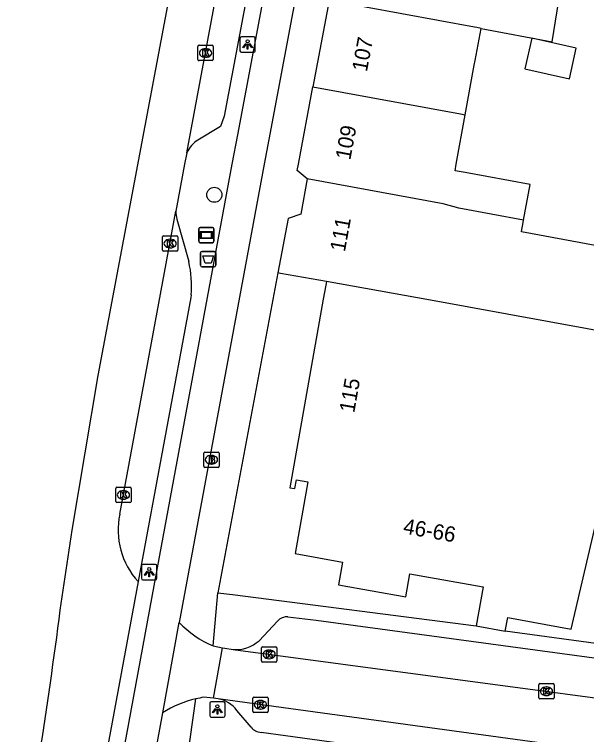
# Model space of a CAD drawing. Extents: x 161845 to 162341, y 381620 to 382158.
# Drawn here: x 161855.67 to 161892.92, y 381712.86 to 381759.75 of the extents above; entities that cross this region are included whole.
import ezdxf

# ---------------------------------------------------------------- set-up
doc = ezdxf.new("R2010")
doc.units = 0
for name, color, linetype in [('IMGEO_Afvalbak', 7, 'Continuous'), ('IMGEO_Boom', 7, 'Continuous'), ('IMGEO_Brandkraan', 7, 'Continuous'), ('IMGEO_Fietspad_gesloten', 7, 'Continuous'), ('IMGEO_Kolk', 7, 'Continuous'), ('IMGEO_Lichtpunt', 7, 'Continuous'), ('IMGEO_OVBaan_gesloten', 7, 'Continuous'), ('IMGEO_OVBaan_open', 7, 'Continuous'), ('IMGEO_Pand', 7, 'Continuous'), ('IMGEO_Pand_nummerreeks', 7, 'Continuous'), ('IMGEO_Parkeervlak_open', 7, 'Continuous'), ('IMGEO_Reclamebord', 7, 'Continuous'), ('IMGEO_Rijbaan_lokaal_gesloten', 7, 'Continuous'), ('IMGEO_Rijbaan_lokaal_open', 7, 'Continuous'), ('IMGEO_Voetpad_open', 7, 'Continuous')]:
    doc.layers.add(name, color=color, linetype=linetype)

msp = doc.modelspace()

# ---------------------------------------------------------------- linework, layer by layer
at = {"layer": 'IMGEO_Afvalbak'}
for p, q in [((161867.787, 381743.416), (161867.787, 381744.216)), ((161867.787, 381744.216), (161867.787, 381743.416)), ((161867.887, 381744.316), (161868.677, 381744.316)), ((161868.677, 381744.316), (161867.887, 381744.316)), ((161868.777, 381744.216), (161868.777, 381743.416)), ((161868.777, 381743.416), (161868.777, 381744.216)), ((161868.677, 381743.316), (161867.887, 381743.316)), ((161867.887, 381743.316), (161868.677, 381743.316))]:
    msp.add_line(p, q, dxfattribs=at)
msp.add_lwpolyline([(161867.93, 381744.03), (161868.634, 381744.03), (161868.485, 381743.56), (161868.079, 381743.56), (161867.93, 381744.03)], dxfattribs=at)
for centre, start, end in [((161867.887, 381744.216), 90, 180), ((161867.887, 381744.216), 90, 180), ((161868.677, 381744.216), 0, 90), ((161868.677, 381744.216), 360, 90), ((161867.887, 381743.416), 180, 270), ((161867.887, 381743.416), 180, 270), ((161868.677, 381743.416), 270, 0), ((161868.677, 381743.416), 270, 0)]:
    msp.add_arc(centre, 0.1, start, end, dxfattribs=at)
at = {"layer": 'IMGEO_Boom'}
msp.add_circle((161868.686, 381748.003), 0.489, dxfattribs=at)
at = {"layer": 'IMGEO_Brandkraan'}
for p, q in [((161867.998, 381730.329), (161867.998, 381731.181)), ((161868.073, 381731.255), (161868.925, 381731.255)), ((161868.486, 381731.035), (161868.511, 381731.035)), ((161868.999, 381731.181), (161868.999, 381730.329)), ((161868.509, 381730.475), (161868.484, 381730.475)), ((161868.925, 381730.255), (161868.073, 381730.255))]:
    msp.add_line(p, q, dxfattribs=at)
for points in [[(161867.998, 381730.329), (161867.998, 381731.181)], [(161868.073, 381731.255), (161868.925, 381731.255)], [(161868.346, 381730.955), (161868.346, 381730.555), (161868.559, 381730.555)], [(161868.577, 381730.955), (161868.346, 381730.955)], [(161868.525, 381730.874), (161868.471, 381730.874), (161868.471, 381730.798)], [(161868.999, 381731.181), (161868.999, 381730.329)], [(161868.471, 381730.798), (161868.524, 381730.798)], [(161868.533, 381730.722), (161868.471, 381730.722), (161868.471, 381730.641)], [(161868.471, 381730.641), (161868.533, 381730.641)], [(161868.925, 381730.255), (161868.073, 381730.255)]]:
    msp.add_lwpolyline(points, dxfattribs=at)
for centre, radius, start, end in [((161868.075, 381731.179), 0.0765, 91.552, 178.448), ((161868.075, 381731.179), 0.0765, 91.552, 178.448), ((161868.526, 381730.836), 0.0379, 267.8285, 90.9355), ((161868.581, 381730.81), 0.145, 59.4692, 91.5367), ((161868.606, 381730.857), 0.0922, 285.5137, 58.1501), ((161868.923, 381731.179), 0.0765, 1.552, 88.448), ((161868.923, 381731.179), 0.0765, 1.552, 88.448), ((161868.534, 381730.681), 0.0404, 269.8759, 90.5077), ((161868.565, 381730.806), 0.251, 268.6676, 293.5347), ((161868.611, 381730.665), 0.105, 301.3115, 78.989), ((161868.075, 381730.331), 0.0765, 181.552, 268.448), ((161868.075, 381730.331), 0.0765, 181.552, 268.448), ((161868.923, 381730.331), 0.0765, 271.552, 358.448), ((161868.923, 381730.331), 0.0765, 271.552, 358.448)]:
    msp.add_arc(centre, radius, start, end, dxfattribs=at)
for centre, major_axis, ratio, start_param, end_param in [((161868.485, 381730.755), (-0.387, 0.002), 0.722429, 4.712389, 7.853982), ((161868.51, 381730.755), (-0.39, 0.002), 0.717154, 1.570796, 4.712389)]:
    msp.add_ellipse(centre, major_axis=major_axis, ratio=ratio, start_param=start_param, end_param=end_param, dxfattribs=at)
at = {"layer": 'IMGEO_Fietspad_gesloten'}
for points in [[(161857.316, 381682.246), (161862.987, 381712.892), (161864.774, 381722.548), (161869.854, 381750), (161870.207, 381751.91), (161895.081, 381884.229), (161897.858, 381899.101), (161916.698, 382000), (161921.558, 382026.031), (161926.346, 382051.921)], [(161907.39, 381938.834), (161899.866, 381898.705), (161897.095, 381883.929), (161872.236, 381751.615), (161871.936, 381750), (161866.402, 381720.165)], [(161859.158, 381680.785), (161865.321, 381714.277)]]:
    msp.add_lwpolyline(points, dxfattribs=at)
at = {"layer": 'IMGEO_Kolk'}
for p, q in [((161867.613, 381756.812), (161867.613, 381757.664)), ((161867.688, 381757.738), (161868.54, 381757.738)), ((161868.614, 381757.664), (161868.614, 381756.812)), ((161868.101, 381757.518), (161868.126, 381757.518)), ((161868.54, 381756.738), (161867.688, 381756.738)), ((161868.124, 381756.958), (161868.099, 381756.958)), ((161865.307, 381744.406), (161865.307, 381745.258)), ((161865.382, 381745.332), (161866.234, 381745.332)), ((161865.795, 381745.112), (161865.82, 381745.112)), ((161866.308, 381745.258), (161866.308, 381744.406)), ((161865.818, 381744.552), (161865.793, 381744.552)), ((161866.234, 381744.332), (161865.382, 381744.332)), ((161862.266, 381728.037), (161862.266, 381728.889)), ((161862.341, 381728.963), (161863.193, 381728.963)), ((161862.754, 381728.743), (161862.779, 381728.743)), ((161863.267, 381728.889), (161863.267, 381728.037)), ((161862.777, 381728.183), (161862.752, 381728.183)), ((161863.193, 381727.963), (161862.341, 381727.963)), ((161871.754, 381717.654), (161871.754, 381718.506)), ((161871.829, 381718.58), (161872.681, 381718.58)), ((161872.242, 381718.36), (161872.267, 381718.36)), ((161872.755, 381718.506), (161872.755, 381717.654)), ((161872.265, 381717.8), (161872.24, 381717.8)), ((161872.681, 381717.58), (161871.829, 381717.58)), ((161889.808, 381715.255), (161889.808, 381716.107)), ((161889.883, 381716.181), (161890.735, 381716.181)), ((161890.296, 381715.961), (161890.321, 381715.961)), ((161890.809, 381716.107), (161890.809, 381715.255)), ((161890.319, 381715.401), (161890.294, 381715.401)), ((161871.187, 381714.373), (161871.187, 381715.225)), ((161871.262, 381715.299), (161872.114, 381715.299)), ((161871.675, 381715.079), (161871.7, 381715.079)), ((161872.188, 381715.225), (161872.188, 381714.373)), ((161890.735, 381715.181), (161889.883, 381715.181)), ((161871.698, 381714.519), (161871.673, 381714.519)), ((161872.114, 381714.299), (161871.262, 381714.299))]:
    msp.add_line(p, q, dxfattribs=at)
for points in [[(161867.613, 381756.812), (161867.613, 381757.664)], [(161867.688, 381757.738), (161868.54, 381757.738)], [(161868.614, 381757.664), (161868.614, 381756.812)], [(161867.934, 381757.438), (161868.057, 381757.438), (161868.057, 381757.287), (161868.187, 381757.438), (161868.351, 381757.438), (161868.205, 381757.287), (161868.358, 381757.038), (161868.206, 381757.038), (161868.121, 381757.202), (161868.057, 381757.135), (161868.057, 381757.038), (161867.934, 381757.038), (161867.934, 381757.438)], [(161868.54, 381756.738), (161867.688, 381756.738)], [(161865.307, 381744.406), (161865.307, 381745.258)], [(161865.382, 381745.332), (161866.234, 381745.332)], [(161865.628, 381745.032), (161865.751, 381745.032), (161865.751, 381744.881), (161865.881, 381745.032), (161866.045, 381745.032), (161865.899, 381744.881), (161866.052, 381744.632), (161865.9, 381744.632), (161865.815, 381744.796), (161865.751, 381744.729), (161865.751, 381744.632), (161865.628, 381744.632), (161865.628, 381745.032)], [(161866.308, 381745.258), (161866.308, 381744.406)], [(161866.234, 381744.332), (161865.382, 381744.332)], [(161862.266, 381728.037), (161862.266, 381728.889)], [(161862.341, 381728.963), (161863.193, 381728.963)], [(161862.587, 381728.663), (161862.71, 381728.663), (161862.71, 381728.512), (161862.84, 381728.663), (161863.004, 381728.663), (161862.858, 381728.512), (161863.011, 381728.263), (161862.859, 381728.263), (161862.774, 381728.427), (161862.71, 381728.36), (161862.71, 381728.263), (161862.587, 381728.263), (161862.587, 381728.663)], [(161863.267, 381728.889), (161863.267, 381728.037)], [(161863.193, 381727.963), (161862.341, 381727.963)], [(161871.754, 381717.654), (161871.754, 381718.506)], [(161871.829, 381718.58), (161872.681, 381718.58)], [(161872.075, 381718.28), (161872.198, 381718.28), (161872.198, 381718.129), (161872.328, 381718.28), (161872.492, 381718.28), (161872.346, 381718.129), (161872.499, 381717.88), (161872.347, 381717.88), (161872.262, 381718.044), (161872.198, 381717.977), (161872.198, 381717.88), (161872.075, 381717.88), (161872.075, 381718.28)], [(161872.755, 381718.506), (161872.755, 381717.654)], [(161872.681, 381717.58), (161871.829, 381717.58)], [(161889.808, 381715.255), (161889.808, 381716.107)], [(161889.883, 381716.181), (161890.735, 381716.181)], [(161890.129, 381715.881), (161890.252, 381715.881), (161890.252, 381715.73), (161890.382, 381715.881), (161890.546, 381715.881), (161890.4, 381715.73), (161890.553, 381715.481), (161890.401, 381715.481), (161890.316, 381715.645), (161890.252, 381715.578), (161890.252, 381715.481), (161890.129, 381715.481), (161890.129, 381715.881)], [(161890.809, 381716.107), (161890.809, 381715.255)], [(161871.187, 381714.373), (161871.187, 381715.225)], [(161871.262, 381715.299), (161872.114, 381715.299)], [(161871.508, 381714.999), (161871.631, 381714.999), (161871.631, 381714.848), (161871.761, 381714.999), (161871.925, 381714.999), (161871.779, 381714.848), (161871.932, 381714.599), (161871.78, 381714.599), (161871.695, 381714.763), (161871.631, 381714.696), (161871.631, 381714.599), (161871.508, 381714.599), (161871.508, 381714.999)], [(161872.188, 381715.225), (161872.188, 381714.373)], [(161890.735, 381715.181), (161889.883, 381715.181)], [(161872.114, 381714.299), (161871.262, 381714.299)]]:
    msp.add_lwpolyline(points, dxfattribs=at)
for centre, start, end in [((161867.69, 381757.662), 91.552, 178.448), ((161867.69, 381757.662), 91.552, 178.448), ((161868.538, 381757.662), 1.552, 88.448), ((161868.538, 381757.662), 1.552, 88.448), ((161867.69, 381756.814), 181.552, 268.448), ((161867.69, 381756.814), 181.552, 268.448), ((161868.538, 381756.814), 271.552, 358.448), ((161868.538, 381756.814), 271.552, 358.448), ((161865.384, 381745.256), 91.552, 178.448), ((161865.384, 381745.256), 91.552, 178.448), ((161866.232, 381745.256), 1.552, 88.448), ((161866.232, 381745.256), 1.552, 88.448), ((161865.384, 381744.408), 181.552, 268.448), ((161865.384, 381744.408), 181.552, 268.448), ((161866.232, 381744.408), 271.552, 358.448), ((161866.232, 381744.408), 271.552, 358.448), ((161862.343, 381728.887), 91.552, 178.448), ((161862.343, 381728.887), 91.552, 178.448), ((161863.191, 381728.887), 1.552, 88.448), ((161863.191, 381728.887), 1.552, 88.448), ((161862.343, 381728.039), 181.552, 268.448), ((161862.343, 381728.039), 181.552, 268.448), ((161863.191, 381728.039), 271.552, 358.448), ((161863.191, 381728.039), 271.552, 358.448), ((161871.831, 381718.504), 91.552, 178.448), ((161871.831, 381718.504), 91.552, 178.448), ((161872.679, 381718.504), 1.552, 88.448), ((161872.679, 381718.504), 1.552, 88.448), ((161871.831, 381717.656), 181.552, 268.448), ((161871.831, 381717.656), 181.552, 268.448), ((161872.679, 381717.656), 271.552, 358.448), ((161872.679, 381717.656), 271.552, 358.448), ((161889.885, 381716.105), 91.552, 178.448), ((161889.885, 381716.105), 91.552, 178.448), ((161890.733, 381716.105), 1.552, 88.448), ((161890.733, 381716.105), 1.552, 88.448), ((161871.264, 381715.223), 91.552, 178.448), ((161871.264, 381715.223), 91.552, 178.448), ((161872.112, 381715.223), 1.552, 88.448), ((161872.112, 381715.223), 1.552, 88.448), ((161889.885, 381715.257), 181.552, 268.448), ((161889.885, 381715.257), 181.552, 268.448), ((161890.733, 381715.257), 271.552, 358.448), ((161890.733, 381715.257), 271.552, 358.448), ((161871.264, 381714.375), 181.552, 268.448), ((161871.264, 381714.375), 181.552, 268.448), ((161872.112, 381714.375), 271.552, 358.448), ((161872.112, 381714.375), 271.552, 358.448)]:
    msp.add_arc(centre, 0.0765, start, end, dxfattribs=at)
for centre, major_axis, ratio, start_param, end_param in [((161868.1, 381757.238), (-0.387, 0.002), 0.722429, 4.712389, 7.853982), ((161868.125, 381757.238), (-0.39, 0.002), 0.717154, 1.570796, 4.712389), ((161865.794, 381744.832), (-0.387, 0.002), 0.722429, 4.712389, 7.853982), ((161865.819, 381744.832), (-0.39, 0.002), 0.717154, 1.570796, 4.712389), ((161862.753, 381728.463), (-0.387, 0.002), 0.722429, 4.712389, 7.853982), ((161862.778, 381728.463), (-0.39, 0.002), 0.717154, 1.570796, 4.712389), ((161872.241, 381718.08), (-0.387, 0.002), 0.722429, 4.712389, 7.853982), ((161872.266, 381718.08), (-0.39, 0.002), 0.717154, 1.570796, 4.712389), ((161890.295, 381715.681), (-0.387, 0.002), 0.722429, 4.712389, 7.853982), ((161890.32, 381715.681), (-0.39, 0.002), 0.717154, 1.570796, 4.712389), ((161871.674, 381714.799), (-0.387, 0.002), 0.722429, 4.712389, 7.853982), ((161871.699, 381714.799), (-0.39, 0.002), 0.717154, 1.570796, 4.712389)]:
    msp.add_ellipse(centre, major_axis=major_axis, ratio=ratio, start_param=start_param, end_param=end_param, dxfattribs=at)
at = {"layer": 'IMGEO_Lichtpunt'}
for p, q in [((161870.351, 381758.194), (161870.351, 381757.387)), ((161870.351, 381758.194), (161870.351, 381757.387)), ((161871.253, 381758.289), (161870.445, 381758.289)), ((161871.253, 381758.289), (161870.445, 381758.289)), ((161871.347, 381757.387), (161871.347, 381758.194)), ((161871.347, 381757.387), (161871.347, 381758.194)), ((161870.445, 381757.293), (161871.253, 381757.293)), ((161870.445, 381757.293), (161871.253, 381757.293)), ((161863.946, 381723.839), (161863.946, 381723.032)), ((161863.946, 381723.839), (161863.946, 381723.032)), ((161864.848, 381723.934), (161864.04, 381723.934)), ((161864.848, 381723.934), (161864.04, 381723.934)), ((161864.942, 381723.032), (161864.942, 381723.839)), ((161864.942, 381723.032), (161864.942, 381723.839)), ((161864.04, 381722.938), (161864.848, 381722.938)), ((161864.04, 381722.938), (161864.848, 381722.938)), ((161869.288, 381714.992), (161868.48, 381714.992)), ((161869.288, 381714.992), (161868.48, 381714.992)), ((161868.386, 381714.897), (161868.386, 381714.09)), ((161868.386, 381714.897), (161868.386, 381714.09)), ((161869.382, 381714.09), (161869.382, 381714.897)), ((161869.382, 381714.09), (161869.382, 381714.897)), ((161868.48, 381713.996), (161869.288, 381713.996)), ((161868.48, 381713.996), (161869.288, 381713.996))]:
    msp.add_line(p, q, dxfattribs=at)
for points in [[(161870.725, 381757.858), (161870.764, 381757.83), (161870.576, 381757.568), (161870.538, 381757.595), (161870.725, 381757.858)], [(161870.827, 381757.81), (161870.874, 381757.81), (161870.874, 381757.488), (161870.827, 381757.488), (161870.827, 381757.81)], [(161870.937, 381757.83), (161870.975, 381757.857), (161871.162, 381757.595), (161871.123, 381757.567), (161870.937, 381757.83)], [(161864.32, 381723.503), (161864.359, 381723.475), (161864.171, 381723.213), (161864.133, 381723.24), (161864.32, 381723.503)], [(161864.422, 381723.455), (161864.469, 381723.455), (161864.469, 381723.133), (161864.422, 381723.133), (161864.422, 381723.455)], [(161864.532, 381723.475), (161864.57, 381723.502), (161864.757, 381723.24), (161864.718, 381723.212), (161864.532, 381723.475)], [(161868.76, 381714.561), (161868.799, 381714.533), (161868.611, 381714.271), (161868.573, 381714.298), (161868.76, 381714.561)], [(161868.862, 381714.513), (161868.909, 381714.513), (161868.909, 381714.191), (161868.862, 381714.191), (161868.862, 381714.513)], [(161868.972, 381714.533), (161869.01, 381714.56), (161869.197, 381714.298), (161869.158, 381714.27), (161868.972, 381714.533)]]:
    msp.add_lwpolyline(points, dxfattribs=at)
for centre in [(161870.85, 381757.992), (161864.445, 381723.637), (161868.885, 381714.695)]:
    msp.add_circle(centre, 0.0994, dxfattribs=at)
for centre, start, end in [((161870.445, 381758.194), 90, 180), ((161870.445, 381758.194), 90, 180), ((161871.253, 381758.194), 0, 90), ((161871.253, 381758.194), 0, 90), ((161870.445, 381757.387), 180, 270), ((161870.445, 381757.387), 180, 270), ((161871.253, 381757.387), 270, 0), ((161871.253, 381757.387), 270, 360), ((161864.04, 381723.839), 90, 180), ((161864.04, 381723.839), 90, 180), ((161864.848, 381723.839), 0, 90), ((161864.848, 381723.839), 0, 90), ((161864.04, 381723.032), 180, 270), ((161864.04, 381723.032), 180, 270), ((161864.848, 381723.032), 270, 0), ((161864.848, 381723.032), 270, 360), ((161868.48, 381714.897), 90, 180), ((161868.48, 381714.897), 90, 180), ((161869.288, 381714.897), 0, 90), ((161869.288, 381714.897), 0, 90), ((161868.48, 381714.09), 180, 270), ((161868.48, 381714.09), 180, 270), ((161869.288, 381714.09), 270, 0), ((161869.288, 381714.09), 270, 360)]:
    msp.add_arc(centre, 0.0946, start, end, dxfattribs=at)
at = {"layer": 'IMGEO_OVBaan_gesloten'}
msp.add_lwpolyline([(161858.651, 381720.96), (161859.425, 381726.158), (161861.132, 381736.231), (161869.606, 381781.344), (161897.211, 381928.16), (161915.531, 382025.949), (161915.767, 382027.092)], dxfattribs=at)
msp.add_arc((161552.98, 381759.757), 308.123, 349.22229, 352.7665, dxfattribs=at)
at = {"layer": 'IMGEO_OVBaan_open'}
for points in [[(161862.533, 381727.211), (161866.175, 381746.944)], [(161866.247, 381746.424), (161867.019, 381743.652)], [(161867.182, 381741.481), (161867.15, 381741.313), (161863.721, 381722.825)]]:
    msp.add_lwpolyline(points, dxfattribs=at)
for centre, radius, start, end in [((161867.977, 381746.929), 1.802, 179.5084, 196.2579), ((161860.197, 381742.048), 7.008, 355.3577, 13.2298), ((161867.337, 381726.158), 4.918, 167.6427, 222.6685)]:
    msp.add_arc(centre, radius, start, end, dxfattribs=at)
at = {"layer": 'IMGEO_Pand'}
for points in [[(161886.047, 381758.842), (161890.679, 381757.965), (161891.624, 381763.915)], [(161876.159, 381760.654), (161875.101, 381755.029)], [(161886.047, 381758.842), (161885.767, 381758.895), (161885.618, 381758.922), (161876.159, 381760.654)], [(161885.019, 381753.201), (161885.608, 381756.435), (161885.666, 381756.751), (161886.047, 381758.842)], [(161892.25, 381757.56), (161889.36, 381758.212), (161888.909, 381756.213), (161891.798, 381755.561), (161892.25, 381757.56)], [(161874.727, 381749.038), (161874.078, 381749.589), (161874.155, 381750), (161875.101, 381755.029)], [(161875.101, 381755.029), (161884.714, 381753.269), (161885.019, 381753.201)], [(161888.814, 381746.358), (161889.239, 381748.671), (161885.018, 381749.447), (161884.356, 381749.569), (161884.435, 381750), (161885.019, 381753.201)], [(161874.727, 381749.038), (161874.307, 381746.749), (161873.489, 381746.458), (161872.827, 381742.933)], [(161888.814, 381746.358), (161884.593, 381747.134), (161883.593, 381747.414), (161874.727, 381749.038)], [(161895.471, 381738.811), (161896.758, 381744.105), (161888.673, 381745.589), (161888.7, 381745.739), (161888.742, 381745.964), (161888.762, 381746.077), (161888.814, 381746.358)], [(161875.98, 381742.352), (161872.993, 381742.884), (161872.827, 381742.933)], [(161875.98, 381742.352), (161875.937, 381742.11), (161875.779, 381741.216), (161873.608, 381728.93), (161873.926, 381728.874), (161874.026, 381729.438), (161874.777, 381729.306), (161873.953, 381724.639), (161877.038, 381724.095), (161876.775, 381722.602), (161881.147, 381721.831), (161881.41, 381723.315), (161886.186, 381722.471), (161885.74, 381719.94)], [(161895.471, 381738.811), (161882.761, 381741.144), (161875.98, 381742.352)], [(161887.622, 381719.595), (161887.784, 381720.479), (161891.913, 381719.721), (161893.893, 381728.171), (161908.006, 381724.477), (161906.933, 381720.378), (161912.06, 381719.035), (161913.133, 381723.134)], [(161885.74, 381719.94), (161887.622, 381719.595)]]:
    msp.add_lwpolyline(points, dxfattribs=at)
at = {"layer": 'IMGEO_Parkeervlak_open'}
msp.add_lwpolyline([(161872.113, 381767.878), (161869.329, 381753.124), (161869.093, 381752.446), (161867.616, 381751.571)], dxfattribs=at)
msp.add_arc((161868.661, 381749.96), 1.921, 122.968, 156.1916, dxfattribs=at)
at = {"layer": 'IMGEO_Reclamebord'}
for p, q in [((161867.766, 381745.88), (161868.556, 381745.88)), ((161868.556, 381745.88), (161867.766, 381745.88)), ((161867.666, 381744.98), (161867.666, 381745.78)), ((161867.666, 381745.78), (161867.666, 381744.98)), ((161868.656, 381745.78), (161868.656, 381744.98)), ((161868.656, 381744.98), (161868.656, 381745.78)), ((161868.556, 381744.88), (161867.766, 381744.88)), ((161867.766, 381744.88), (161868.556, 381744.88))]:
    msp.add_line(p, q, dxfattribs=at)
for points in [[(161867.767, 381745.612), (161868.555, 381745.612), (161868.555, 381745.148), (161867.767, 381745.148), (161867.767, 381745.612)], [(161867.832, 381745.547), (161867.832, 381745.213), (161868.49, 381745.213), (161868.49, 381745.547), (161867.832, 381745.547)]]:
    msp.add_lwpolyline(points, dxfattribs=at)
for centre, start, end in [((161867.766, 381745.78), 90, 180), ((161867.766, 381745.78), 90, 180), ((161868.556, 381745.78), 0, 90), ((161868.556, 381745.78), 360, 90), ((161867.766, 381744.98), 180, 270), ((161867.766, 381744.98), 180, 270), ((161868.556, 381744.98), 270, 0), ((161868.556, 381744.98), 270, 0)]:
    msp.add_arc(centre, 0.1, start, end, dxfattribs=at)
at = {"layer": 'IMGEO_Rijbaan_lokaal_gesloten'}
for points in [[(161866.904, 381750.735), (161870.759, 381771.481)], [(161866.904, 381750.735), (161866.739, 381750), (161866.175, 381746.944)], [(161863.721, 381722.825), (161861.927, 381713.087), (161861.385, 381710.143), (161860.718, 381707.24), (161860.66, 381706.996), (161860.336, 381705.821)]]:
    msp.add_lwpolyline(points, dxfattribs=at)
at = {"layer": 'IMGEO_Rijbaan_lokaal_open'}
for points in [[(161865.321, 381714.277), (161866.402, 381720.165)], [(161868.609, 381718.629), (161869.225, 381718.514)], [(161868.626, 381715.237), (161869.225, 381718.514)], [(161869.225, 381718.514), (161869.365, 381718.483), (161869.911, 381718.389)], [(161869.911, 381718.389), (161898.507, 381714.581)], [(161868.626, 381715.237), (161867.989, 381715.284)], [(161868.939, 381715.193), (161868.626, 381715.237)], [(161909.378, 381709.658), (161873.668, 381714.537), (161868.939, 381715.193)]]:
    msp.add_lwpolyline(points, dxfattribs=at)
for centre, radius, start, end in [((161871.05, 381724.49), 6.349, 222.9381, 247.3886), ((161869.087, 381708.336), 7.034, 103.2185, 122.3752), ((161869.008, 381708.739), 6.624, 98.8455, 103.342)]:
    msp.add_arc(centre, radius, start, end, dxfattribs=at)
at = {"layer": 'IMGEO_Voetpad_open'}
for points in [[(161872.827, 381742.933), (161868.92, 381722.091)], [(161868.609, 381718.629), (161868.92, 381722.091)], [(161868.92, 381722.091), (161869.859, 381721.971), (161885.74, 381719.94)], [(161871.6, 381718.966), (161872.79, 381720.242)], [(161873.478, 381720.533), (161875.325, 381720.308), (161898.861, 381717.122)], [(161898.959, 381718.053), (161887.622, 381719.595)], [(161866.911, 381711.167), (161867.479, 381715.184)], [(161871.079, 381713.333), (161870.151, 381714.435)], [(161906.334, 381708.242), (161873.323, 381712.777), (161871.736, 381712.996)]]:
    msp.add_lwpolyline(points, dxfattribs=at)
for centre, radius, start, end in [((161873.469, 381719.595), 0.938, 89.471, 136.3823), ((161870.043, 381720.762), 2.376, 266.804, 310.9186), ((161868.565, 381713.248), 1.981, 36.8255, 79.1297), ((161871.788, 381713.907), 0.912, 218.9737, 266.7163)]:
    msp.add_arc(centre, radius, start, end, dxfattribs=at)

# ---------------------------------------------------------------- texts
at = {"layer": 'IMGEO_Pand_nummerreeks'}
for s, rotation, p in [('107', 79.3489, (161878.615, 381755.97)), ('109', 79.3468, (161877.535, 381750.228)), ('111', 79.601, (161877.183, 381744.249)), ('115', 79.9792, (161877.794, 381733.772)), ('46-66', 349.9618, (161880.932, 381725.962))]:
    msp.add_text(s, height=1, rotation=rotation, dxfattribs=at).set_placement(p)

doc.saveas('drawing.dxf')
